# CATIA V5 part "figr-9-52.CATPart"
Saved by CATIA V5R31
Part number: Part1
Bounding box of the stored display mesh (mm): x -121 to 121, y -90 to 90, z -40 to 40
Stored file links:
  D:\PROJECTS\Project 2021\US EDITION\CATIA V5 6R 2021\Resources\Part Files\c09_catia_v5_6r2021_prt\c09_catia_v5_6r2021_prt\figr-9-52.CATPart
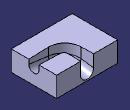
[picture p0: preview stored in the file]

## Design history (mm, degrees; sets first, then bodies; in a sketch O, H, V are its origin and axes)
Body1 (main body)
  Sketch1 on yz-plane, origin (0, 0, 0), H (0, 1, 0), V (0, 0, 1)
    line L1 (-90, 40) -> (90, 40)
    line L2 (90, 40) -> (90, -40)
    line L3 (90, -40) -> (-90, -40)
    line L4 (-90, -40) -> (-90, 40)
    axis line L5 (90, -40) -> (-90, 40)
    horizontal: L1 H, L3 H
    vertical: L2 V, L4 V
    midpoint: O L5
  Pad1: profile Sketch1, direction (1, 0, 0), length 121, mirrored extent
  Loft1: solid, Sections (Sketch4; Sketch3), Spine Sketch2, SectionCouplingPoints ({coupling CouplingPoints (vertex [element of Sketch4 | element of Sketch4]; vertex [element of Sketch3 | element of Sketch3])}; {coupling CouplingPoints (vertex [element of Sketch4 | element of Sketch4]; vertex [element of Sketch3 | element of Sketch3])}; {coupling CouplingPoints (vertex [element of Sketch4 | element of Sketch4]; vertex [element of Sketch3 | element of Sketch3])})
  Sketch2 on face of Pad1, origin (0, 0, 40), H (1, 0, 0), V (0, 1, 0)
    point P1 (121, 0)
    line L1 (121, 0) -> (40.984, 0)
    arc A1 centre (40.984, 40.984) radius 40.984 from (40.984, 0) to (0, 40.984) cw
    line L2 (0, 40.984) -> (0, 90)
    point P5 (0, 90)
    reference projected line E1 (121, 20) -> (121, -20) from edge of Sketch4
    reference projected line E2 (-25.9516, 90) -> (25.9516, 90) from edge of Sketch3
    coincidence: P1 H, P1 E1, P5 E2
    horizontal: L1 H
    tangency: A1 L1, L2 A1
    vertical: L2 V
  Sketch3 on face of Pad1, origin (0, 90, 0), H (-1, 0, 0), V (0, 0, 1)
    line L1 (-25.9516, 40) -> (-25.9516, -8.0968)
    arc A1 centre (0, -8.0968) radius 25.9516 from (-25.9516, -8.0968) to (25.9516, -8.0968) ccw
    point P3 (0, -8.0968)
    line L2 (25.9516, -8.0968) -> (25.9516, 40)
    line L3 (25.9516, 40) -> (-25.9516, 40)
    reference projected line E1 (121, 40) -> (-121, 40) from edge [face of Pad1 | face of Pad1]
    vertical: L1 V, L2 V
    tangency: A1 L1, L2 A1
    horizontal: L3 H
    coincidence: P3 V, L3 E1
  Sketch4 on face of Pad1, origin (121, 0, 0), H (0, 1, 0), V (0, 0, 1)
    line L1 (-20, 40) -> (-20, 21.9917)
    arc A1 centre (0, 21.9917) radius 20 from (-20, 21.9917) to (20, 21.9917) ccw
    point P3 (0, 21.9917)
    line L2 (20, 21.9917) -> (20, 40)
    line L3 (20, 40) -> (-20, 40)
    reference projected line E1 (90, 40) -> (-90, 40) from edge [face of Pad1 | face of Pad1]
    vertical: L1 V, L2 V
    tangency: A1 L1, L2 A1
    horizontal: L3 H
    coincidence: P3 V, L3 E1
